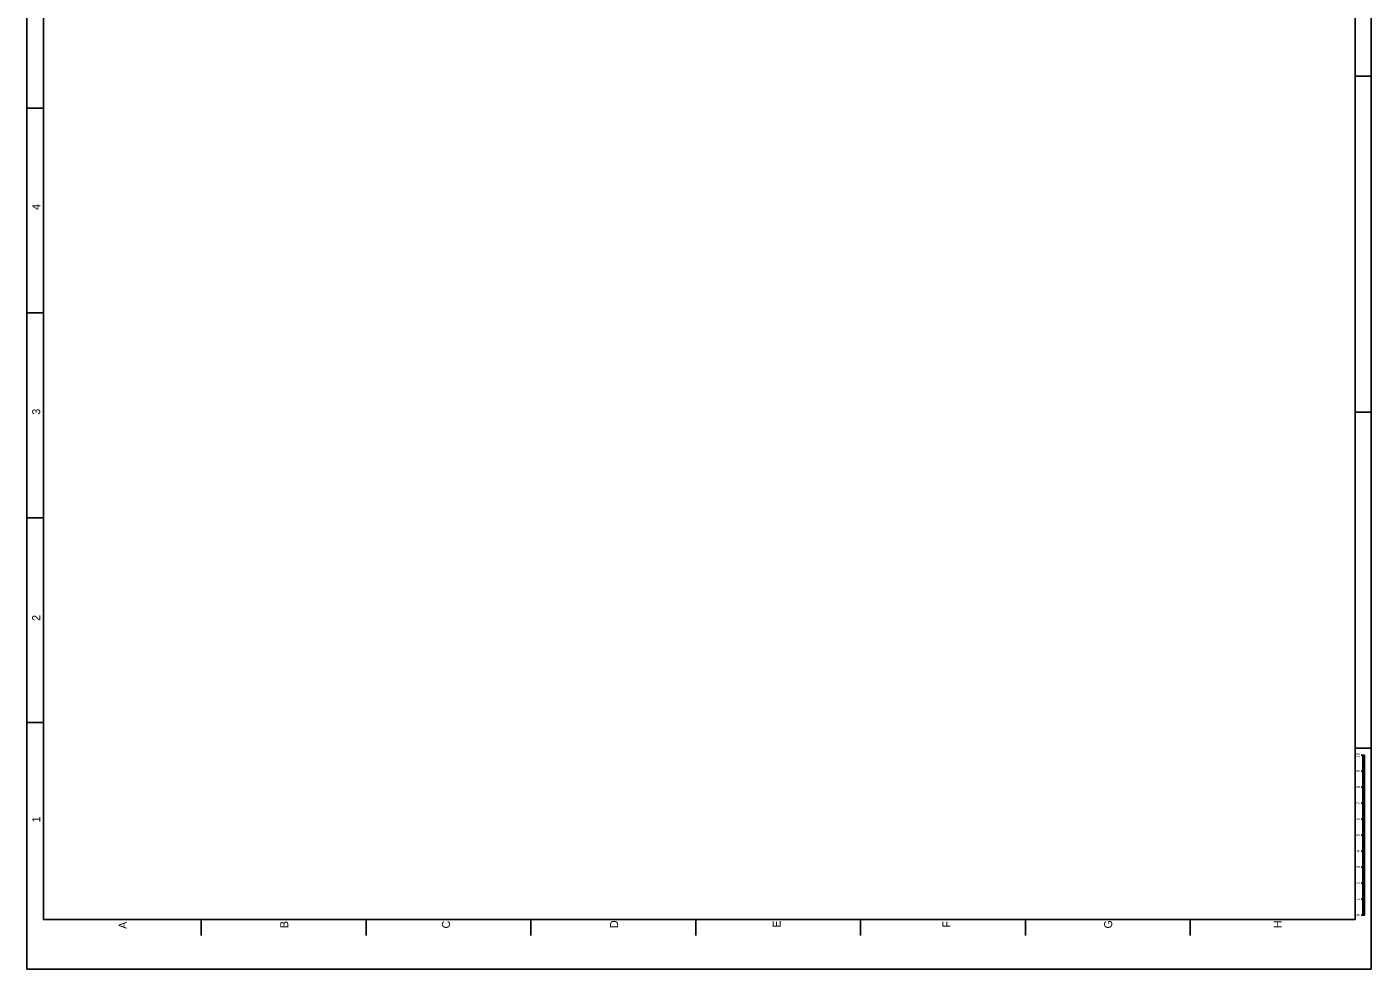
# Model space of a CAD drawing. Extents: x -932963 to -932666, y -737039 to -736000.
# Drawn here: x -932796.9307 to -932796.5107, y -736669.4882 to -736669.1939 of the extents above; entities that cross this region are included whole.
import ezdxf

# ---------------------------------------------------------------- set-up
doc = ezdxf.new("R2010")
doc.units = 0
doc.layers.add('Border', color=7, linetype='Continuous')

# ---------------------------------------------------------------- blocks, each defined once
blk = doc.blocks.new('A0_v03_CZ_1')
at = {"layer": 'Border'}
for p, q in [((0.154, 0.8297), (0.154, 0.8394)), ((0.282, 0.8297), (0.282, 0.8394)), ((0.41, 0.8297), (0.41, 0.8394)), ((0.538, 0.8297), (0.538, 0.8394)), ((0.0209, 0.731), (0.0309, 0.731)), ((0.0209, 0.628), (0.0309, 0.628)), ((0.0209, 0.525), (0.0309, 0.525)), ((0.0209, 0.422), (0.0309, 0.422)), ((0.0209, 0.319), (0.0309, 0.319)), ((0.0209, 0.216), (0.0309, 0.216)), ((0.0209, 0.113), (0.0309, 0.113)), ((0.138, 0), (0.138, 0.01)), ((0.348, 0), (0.348, 0.01)), ((0.558, 0), (0.558, 0.01))]:
    blk.add_line(p, q, dxfattribs=at)
blk.add_lwpolyline([(0, 0), (1.188, 0), (1.188, 0.84), (0, 0.84)], close=True, dxfattribs=at)
for points in [[(0.978, 0.01), (0.0309, 0.01), (0.0309, 0.8297), (1.178, 0.8297), (1.178, 0.297)], [(0.03373, 0.00414), (0.03373, 0.00614)], [(0.04373, 0.00414), (0.04373, 0.00514), (0.03373, 0.00514), (0.03373, 0.00414), (0.04373, 0.00414)], [(0.03373, 0.00514), (0.13373, 0.00514)], [(0.03373, 0.00414), (0.13373, 0.00414)], [(0.04373, 0.00414), (0.04373, 0.00614)], [(0.05373, 0.00414), (0.05373, 0.00614)], [(0.06373, 0.00414), (0.06373, 0.00514), (0.05373, 0.00514), (0.05373, 0.00414), (0.06373, 0.00414)], [(0.06373, 0.00414), (0.06373, 0.00614)], [(0.07373, 0.00414), (0.07373, 0.00614)], [(0.07373, 0.00514), (0.07373, 0.00414), (0.08373, 0.00414), (0.08373, 0.00514), (0.07373, 0.00514)], [(0.08373, 0.00414), (0.08373, 0.00614)], [(0.09373, 0.00414), (0.09373, 0.00614)], [(0.09373, 0.00514), (0.09373, 0.00414), (0.10373, 0.00414), (0.10373, 0.00514), (0.09373, 0.00514)], [(0.10373, 0.00414), (0.10373, 0.00614)], [(0.11373, 0.00414), (0.11373, 0.00614)], [(0.11373, 0.00514), (0.11373, 0.00414), (0.12373, 0.00414), (0.12373, 0.00514), (0.11373, 0.00514)], [(0.12373, 0.00414), (0.12373, 0.00614)], [(0.13373, 0.00414), (0.13373, 0.00614)]]:
    blk.add_lwpolyline(points, dxfattribs=at)
for s, height, p in [('1', 0.005, (0.0917, 0.8317)), ('2', 0.005, (0.2176, 0.8317)), ('3', 0.005, (0.3464, 0.8317)), ('4', 0.005, (0.4743, 0.8317)), ('A', 0.005, (0.02516, 0.7776)), ('B', 0.005, (0.02563, 0.6767)), ('C', 0.005, (0.0254, 0.5756)), ('D', 0.005, (0.02563, 0.4706)), ('E', 0.005, (0.02587, 0.369)), ('F', 0.005, (0.02587, 0.2629)), ('G', 0.005, (0.0254, 0.1618)), ('H', 0.005, (0.02563, 0.056)), ('0', 0.002, (0.03295, 0.00715)), ('1', 0.002, (0.04295, 0.00713)), ('2', 0.002, (0.05295, 0.00713)), ('3', 0.002, (0.06295, 0.00715)), ('4', 0.002, (0.07295, 0.00714)), ('5', 0.002, (0.08295, 0.00717)), ('6', 0.002, (0.09295, 0.00715)), ('7', 0.002, (0.10295, 0.00715)), ('8', 0.002, (0.11295, 0.00715)), ('9', 0.002, (0.12295, 0.00715)), ('10', 0.002, (0.13217, 0.00715))]:
    blk.add_text(s, height=height, dxfattribs=at).set_placement(p)

msp = doc.modelspace()

# ---------------------------------------------------------------- block references
at = {"layer": 'Border', "xscale": 0.5, "yscale": 0.5, "rotation": 90}
msp.add_blockref('A0_v03_CZ_1', (-932796.51074, -736669.48825), dxfattribs=at)

doc.saveas('drawing.dxf')
